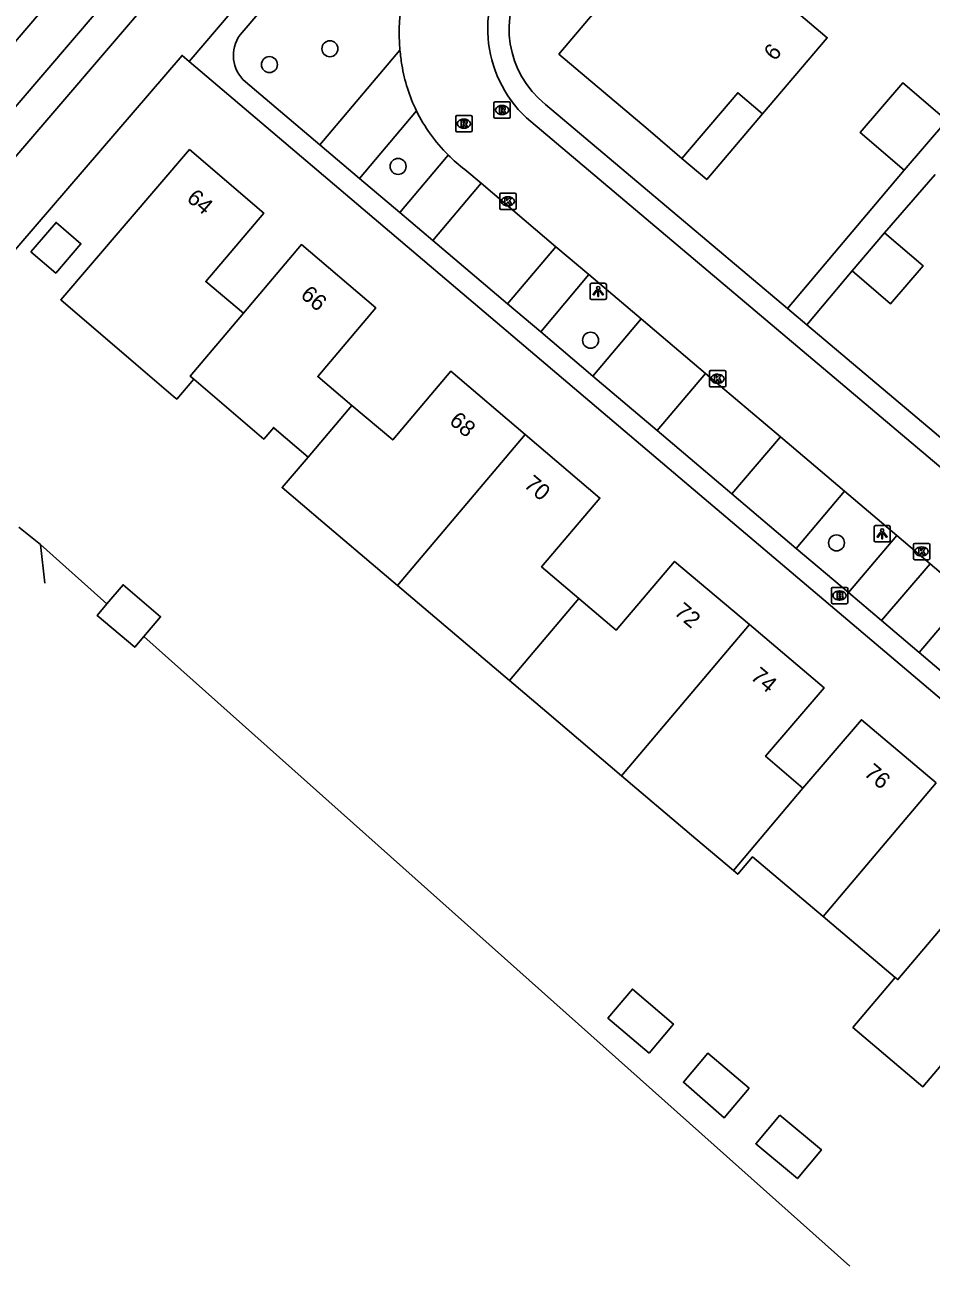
# Model space of a CAD drawing. Extents: x 156414 to 157775, y 382335 to 383765.
# Drawn here: x 156781.6 to 156837.1, y 382383.6 to 382459.6 of the extents above; entities that cross this region are included whole.
import ezdxf

# ---------------------------------------------------------------- set-up
doc = ezdxf.new("R2010")
doc.units = 0
for name, color, linetype in [('IMGEO_Boom', 7, 'Continuous'), ('IMGEO_Brandkraan', 7, 'Continuous'), ('IMGEO_Grasland_overig', 7, 'Continuous'), ('IMGEO_Groenvoorziening', 7, 'Continuous'), ('IMGEO_Kolk', 7, 'Continuous'), ('IMGEO_Lichtpunt', 7, 'Continuous'), ('IMGEO_Pand', 7, 'Continuous'), ('IMGEO_Pand_nummerreeks', 7, 'Continuous'), ('IMGEO_Pand_overbouw', 7, 'Continuous'), ('IMGEO_Parkeervlak_open', 7, 'Continuous'), ('IMGEO_Rijbaan_lokaal_open', 7, 'Continuous'), ('IMGEO_Rioolput', 7, 'Continuous'), ('IMGEO_Sloot', 7, 'Continuous'), ('IMGEO_Voetpad_open', 7, 'Continuous'), ('IMGEO_Waterloop', 7, 'Continuous')]:
    doc.layers.add(name, color=color, linetype=linetype)

msp = doc.modelspace()

# ---------------------------------------------------------------- linework, layer by layer
at = {"layer": 'IMGEO_Boom'}
for centre in [(156800.293, 382458.143), (156796.587, 382457.167), (156804.472, 382450.932), (156816.266, 382440.281), (156831.333, 382427.869)]:
    msp.add_circle(centre, 0.489, dxfattribs=at)
at = {"layer": 'IMGEO_Brandkraan'}
for p, q in [((156831.018, 382424.22), (156831.018, 382425.072)), ((156831.093, 382425.146), (156831.945, 382425.146)), ((156831.506, 382424.926), (156831.531, 382424.926)), ((156832.019, 382425.072), (156832.019, 382424.22)), ((156831.945, 382424.146), (156831.093, 382424.146)), ((156831.529, 382424.366), (156831.504, 382424.366))]:
    msp.add_line(p, q, dxfattribs=at)
for points in [[(156831.018, 382424.22), (156831.018, 382425.072)], [(156831.093, 382425.146), (156831.945, 382425.146)], [(156831.366, 382424.846), (156831.366, 382424.446), (156831.579, 382424.446)], [(156831.597, 382424.846), (156831.366, 382424.846)], [(156831.545, 382424.765), (156831.491, 382424.765), (156831.491, 382424.689)], [(156831.491, 382424.689), (156831.544, 382424.689)], [(156831.553, 382424.613), (156831.491, 382424.613), (156831.491, 382424.532)], [(156832.019, 382425.072), (156832.019, 382424.22)], [(156831.945, 382424.146), (156831.093, 382424.146)], [(156831.491, 382424.532), (156831.553, 382424.532)]]:
    msp.add_lwpolyline(points, dxfattribs=at)
for centre, radius, start, end in [((156831.095, 382425.07), 0.0765, 91.55205, 178.44795), ((156831.095, 382425.07), 0.0765, 91.55205, 178.44795), ((156831.546, 382424.727), 0.0379, 267.82845, 90.93552), ((156831.554, 382424.572), 0.0404, 269.87594, 90.50774), ((156831.601, 382424.701), 0.145, 59.4692, 91.53667), ((156831.626, 382424.748), 0.0922, 285.51372, 58.15012), ((156831.631, 382424.556), 0.105, 301.31148, 78.98903), ((156831.943, 382425.07), 0.0765, 1.55205, 88.44795), ((156831.943, 382425.07), 0.0765, 1.55205, 88.44795), ((156831.095, 382424.222), 0.0765, 181.55205, 268.44795), ((156831.095, 382424.222), 0.0765, 181.55205, 268.44795), ((156831.585, 382424.697), 0.251, 268.66757, 293.53466), ((156831.943, 382424.222), 0.0765, 271.55205, 358.44795), ((156831.943, 382424.222), 0.0765, 271.55205, 358.44795)]:
    msp.add_arc(centre, radius, start, end, dxfattribs=at)
for centre, major_axis, ratio, start_param, end_param in [((156831.505, 382424.646), (-0.387, 0.002), 0.722429, 4.712389, 7.853982), ((156831.53, 382424.646), (-0.39, 0.002), 0.717154, 1.570796, 4.712389)]:
    msp.add_ellipse(centre, major_axis=major_axis, ratio=ratio, start_param=start_param, end_param=end_param, dxfattribs=at)
at = {"layer": 'IMGEO_Grasland_overig'}
for points in [[(156786.631, 382424.138), (156782.557, 382427.77)], [(156832.144, 382383.561), (156788.885, 382422.128)]]:
    msp.add_lwpolyline(points, dxfattribs=at)
at = {"layer": 'IMGEO_Groenvoorziening'}
for points in [[(156820.95, 382498.966), (156818.053, 382495.021), (156800.704, 382474.383), (156791.599, 382463.885), (156773.907, 382443.229)], [(156772.208, 382435.618), (156791.237, 382457.729), (156791.675, 382457.364)]]:
    msp.add_lwpolyline(points, dxfattribs=at)
at = {"layer": 'IMGEO_Kolk'}
for p, q in [((156810.699, 382448.366), (156810.699, 382449.218)), ((156810.774, 382449.292), (156811.626, 382449.292)), ((156811.187, 382449.072), (156811.212, 382449.072)), ((156811.7, 382449.218), (156811.7, 382448.366)), ((156811.626, 382448.292), (156810.774, 382448.292)), ((156811.21, 382448.512), (156811.185, 382448.512)), ((156823.543, 382437.499), (156823.543, 382438.351)), ((156823.618, 382438.425), (156824.47, 382438.425)), ((156824.544, 382438.351), (156824.544, 382437.499)), ((156824.054, 382437.645), (156824.029, 382437.645)), ((156824.031, 382438.205), (156824.056, 382438.205)), ((156824.47, 382437.425), (156823.618, 382437.425)), ((156836.048, 382426.915), (156836.048, 382427.767)), ((156836.123, 382427.841), (156836.975, 382427.841)), ((156836.536, 382427.621), (156836.561, 382427.621)), ((156837.049, 382427.767), (156837.049, 382426.915)), ((156836.559, 382427.061), (156836.534, 382427.061)), ((156836.975, 382426.841), (156836.123, 382426.841))]:
    msp.add_line(p, q, dxfattribs=at)
for points in [[(156810.699, 382448.366), (156810.699, 382449.218)], [(156810.774, 382449.292), (156811.626, 382449.292)], [(156811.02, 382448.992), (156811.143, 382448.992), (156811.143, 382448.841), (156811.273, 382448.992), (156811.437, 382448.992), (156811.291, 382448.841), (156811.444, 382448.592), (156811.292, 382448.592), (156811.207, 382448.756), (156811.143, 382448.689), (156811.143, 382448.592), (156811.02, 382448.592), (156811.02, 382448.992)], [(156811.7, 382449.218), (156811.7, 382448.366)], [(156811.626, 382448.292), (156810.774, 382448.292)], [(156823.543, 382437.499), (156823.543, 382438.351)], [(156823.618, 382438.425), (156824.47, 382438.425)], [(156824.544, 382438.351), (156824.544, 382437.499)], [(156823.864, 382438.125), (156823.987, 382438.125), (156823.987, 382437.974), (156824.117, 382438.125), (156824.281, 382438.125), (156824.135, 382437.974), (156824.288, 382437.725), (156824.136, 382437.725), (156824.051, 382437.889), (156823.987, 382437.822), (156823.987, 382437.725), (156823.864, 382437.725), (156823.864, 382438.125)], [(156824.47, 382437.425), (156823.618, 382437.425)], [(156836.048, 382426.915), (156836.048, 382427.767)], [(156836.123, 382427.841), (156836.975, 382427.841)], [(156837.049, 382427.767), (156837.049, 382426.915)], [(156836.369, 382427.541), (156836.492, 382427.541), (156836.492, 382427.39), (156836.622, 382427.541), (156836.786, 382427.541), (156836.64, 382427.39), (156836.793, 382427.141), (156836.641, 382427.141), (156836.556, 382427.305), (156836.492, 382427.238), (156836.492, 382427.141), (156836.369, 382427.141), (156836.369, 382427.541)], [(156836.975, 382426.841), (156836.123, 382426.841)]]:
    msp.add_lwpolyline(points, dxfattribs=at)
for centre, start, end in [((156810.776, 382449.216), 91.55205, 178.44795), ((156810.776, 382449.216), 91.55205, 178.44795), ((156811.624, 382449.216), 1.55205, 88.44795), ((156811.624, 382449.216), 1.55205, 88.44795), ((156810.776, 382448.368), 181.55205, 268.44795), ((156810.776, 382448.368), 181.55205, 268.44795), ((156811.624, 382448.368), 271.55205, 358.44795), ((156811.624, 382448.368), 271.55205, 358.44795), ((156823.62, 382438.349), 91.55205, 178.44795), ((156823.62, 382438.349), 91.55205, 178.44795), ((156824.468, 382438.349), 1.55205, 88.44795), ((156824.468, 382438.349), 1.55205, 88.44795), ((156823.62, 382437.501), 181.55205, 268.44795), ((156823.62, 382437.501), 181.55205, 268.44795), ((156824.468, 382437.501), 271.55205, 358.44795), ((156824.468, 382437.501), 271.55205, 358.44795), ((156836.125, 382427.765), 91.55205, 178.44795), ((156836.125, 382427.765), 91.55205, 178.44795), ((156836.973, 382427.765), 1.55205, 88.44795), ((156836.973, 382427.765), 1.55205, 88.44795), ((156836.125, 382426.917), 181.55205, 268.44795), ((156836.125, 382426.917), 181.55205, 268.44795), ((156836.973, 382426.917), 271.55205, 358.44795), ((156836.973, 382426.917), 271.55205, 358.44795)]:
    msp.add_arc(centre, 0.0765, start, end, dxfattribs=at)
for centre, major_axis, ratio, start_param, end_param in [((156811.186, 382448.792), (-0.387, 0.002), 0.722429, 4.712389, 7.853982), ((156811.211, 382448.792), (-0.39, 0.002), 0.717154, 1.570796, 4.712389), ((156824.03, 382437.925), (-0.387, 0.002), 0.722429, 4.712389, 7.853982), ((156824.055, 382437.925), (-0.39, 0.002), 0.717154, 1.570796, 4.712389), ((156836.535, 382427.341), (-0.387, 0.002), 0.722429, 4.712389, 7.853982), ((156836.56, 382427.341), (-0.39, 0.002), 0.717154, 1.570796, 4.712389)]:
    msp.add_ellipse(centre, major_axis=major_axis, ratio=ratio, start_param=start_param, end_param=end_param, dxfattribs=at)
at = {"layer": 'IMGEO_Lichtpunt'}
for p, q in [((156816.236, 382443.677), (156816.236, 382442.87)), ((156816.236, 382443.677), (156816.236, 382442.87)), ((156817.138, 382443.772), (156816.33, 382443.772)), ((156817.138, 382443.772), (156816.33, 382443.772)), ((156817.232, 382442.87), (156817.232, 382443.677)), ((156817.232, 382442.87), (156817.232, 382443.677)), ((156816.33, 382442.776), (156817.138, 382442.776)), ((156816.33, 382442.776), (156817.138, 382442.776)), ((156833.632, 382428.832), (156833.632, 382428.025)), ((156833.632, 382428.832), (156833.632, 382428.025)), ((156834.534, 382428.927), (156833.726, 382428.927)), ((156834.534, 382428.927), (156833.726, 382428.927)), ((156834.628, 382428.025), (156834.628, 382428.832)), ((156834.628, 382428.025), (156834.628, 382428.832)), ((156833.726, 382427.931), (156834.534, 382427.931)), ((156833.726, 382427.931), (156834.534, 382427.931))]:
    msp.add_line(p, q, dxfattribs=at)
for points in [[(156816.61, 382443.341), (156816.649, 382443.313), (156816.461, 382443.051), (156816.423, 382443.078), (156816.61, 382443.341)], [(156816.712, 382443.293), (156816.759, 382443.293), (156816.759, 382442.971), (156816.712, 382442.971), (156816.712, 382443.293)], [(156816.822, 382443.313), (156816.86, 382443.34), (156817.047, 382443.078), (156817.008, 382443.05), (156816.822, 382443.313)], [(156834.006, 382428.496), (156834.045, 382428.468), (156833.857, 382428.206), (156833.819, 382428.233), (156834.006, 382428.496)], [(156834.108, 382428.448), (156834.155, 382428.448), (156834.155, 382428.126), (156834.108, 382428.126), (156834.108, 382428.448)], [(156834.218, 382428.468), (156834.256, 382428.495), (156834.443, 382428.233), (156834.404, 382428.205), (156834.218, 382428.468)]]:
    msp.add_lwpolyline(points, dxfattribs=at)
for centre in [(156816.735, 382443.475), (156834.131, 382428.63)]:
    msp.add_circle(centre, 0.0994, dxfattribs=at)
for centre, start, end in [((156816.33, 382443.677), 90, 180), ((156816.33, 382443.677), 90, 180), ((156817.138, 382443.677), 0, 90), ((156817.138, 382443.677), 0, 90), ((156816.33, 382442.87), 180, 270), ((156816.33, 382442.87), 180, 270), ((156817.138, 382442.87), 270, 0), ((156817.138, 382442.87), 270, 360), ((156833.726, 382428.832), 90, 180), ((156833.726, 382428.832), 90, 180), ((156834.534, 382428.832), 0, 90), ((156834.534, 382428.832), 0, 90), ((156833.726, 382428.025), 180, 270), ((156833.726, 382428.025), 180, 270), ((156834.534, 382428.025), 270, 0), ((156834.534, 382428.025), 270, 360)]:
    msp.add_arc(centre, 0.0946, start, end, dxfattribs=at)
at = {"layer": 'IMGEO_Pand'}
for points in [[(156823.603, 382464.901), (156821.52, 382462.535), (156819.671, 382464.14), (156814.326, 382457.818), (156819.783, 382453.194), (156821.862, 382451.425), (156825.278, 382455.442), (156826.802, 382454.147), (156830.766, 382458.81), (156823.603, 382464.901)], [(156838.087, 382453.751), (156835.405, 382456.06), (156832.784, 382453.003), (156835.48, 382450.702)], [(156838.087, 382453.751), (156835.48, 382450.702)], [(156791.957, 382437.897), (156790.909, 382436.674), (156790.691, 382436.861), (156788.408, 382438.819), (156783.803, 382442.767), (156791.692, 382451.968), (156796.235, 382448.073), (156792.687, 382443.876), (156794.997, 382441.95)], [(156781.972, 382445.705), (156783.516, 382447.506), (156785.042, 382446.198), (156783.497, 382444.397), (156781.972, 382445.705)], [(156834.276, 382446.87), (156832.298, 382444.54)], [(156832.298, 382444.54), (156834.638, 382442.513), (156836.632, 382444.85), (156834.276, 382446.87)], [(156794.997, 382441.95), (156798.545, 382446.146), (156803.106, 382442.264), (156799.551, 382438.056), (156801.645, 382436.286)], [(156794.997, 382441.95), (156791.731, 382438.091), (156791.957, 382437.897)], [(156801.645, 382436.286), (156804.14, 382434.178), (156807.696, 382438.387), (156812.265, 382434.503)], [(156798.968, 382433.123), (156796.887, 382434.907), (156796.85, 382434.939), (156796.239, 382434.225), (156791.957, 382437.897)], [(156798.968, 382433.123), (156801.645, 382436.286)], [(156812.265, 382434.503), (156804.439, 382425.255)], [(156812.265, 382434.503), (156816.834, 382430.618), (156813.267, 382426.411), (156815.548, 382424.466)], [(156804.439, 382425.255), (156799.87, 382429.132), (156797.367, 382431.255), (156798.968, 382433.123)], [(156815.548, 382424.466), (156817.829, 382422.522), (156821.414, 382426.737), (156825.995, 382422.864)], [(156786.631, 382424.138), (156787.618, 382425.302), (156789.921, 382423.349), (156788.885, 382422.128)], [(156811.294, 382419.439), (156809.01, 382421.376), (156804.439, 382425.255)], [(156788.885, 382422.128), (156788.332, 382421.476), (156786.03, 382423.429), (156786.631, 382424.138)], [(156815.548, 382424.466), (156811.294, 382419.439)], [(156825.995, 382422.864), (156818.164, 382413.609)], [(156825.995, 382422.864), (156830.576, 382418.991), (156826.992, 382414.794), (156829.278, 382412.835)], [(156818.164, 382413.609), (156813.581, 382417.498), (156811.294, 382419.439)], [(156829.278, 382412.835), (156832.862, 382417.032), (156837.437, 382413.161)], [(156825.016, 382407.795), (156822.721, 382409.742), (156818.164, 382413.609)], [(156825.016, 382407.795), (156829.278, 382412.835)], [(156830.519, 382404.985), (156837.437, 382413.161)], [(156830.519, 382404.985), (156826.195, 382408.644), (156825.284, 382407.567), (156825.016, 382407.795)], [(156842.012, 382409.29), (156835.093, 382401.114), (156834.934, 382401.249)], [(156834.934, 382401.249), (156830.519, 382404.985)], [(156839.668, 382397.243), (156839.223, 382397.62), (156836.63, 382394.555), (156832.341, 382398.184), (156834.934, 382401.249)], [(156819.849, 382396.616), (156817.331, 382398.761), (156818.83, 382400.533), (156821.339, 382398.389), (156819.849, 382396.616)], [(156825.976, 382394.472), (156824.452, 382392.657), (156821.95, 382394.826), (156823.457, 382396.614), (156825.976, 382394.472)], [(156827.866, 382392.822), (156830.411, 382390.691), (156828.934, 382388.931), (156826.381, 382391.059), (156827.866, 382392.822)]]:
    msp.add_lwpolyline(points, dxfattribs=at)
at = {"layer": 'IMGEO_Pand_overbouw'}
msp.add_lwpolyline([(156821.862, 382451.425), (156823.386, 382450.129), (156826.802, 382454.147), (156825.278, 382455.442)], close=True, dxfattribs=at)
at = {"layer": 'IMGEO_Parkeervlak_open'}
for points in [[(156799.666, 382452.263), (156804.586, 382458.056)], [(156805.592, 382454.345), (156802.099, 382450.202)], [(156807.536, 382451.631), (156804.578, 382448.103)], [(156816.15, 382444.311), (156813.213, 382440.791)], [(156816.404, 382438.089), (156819.362, 382441.59)], [(156831.828, 382431.028), (156828.869, 382427.532)], [(156832.065, 382424.824), (156835.024, 382428.321)]]:
    msp.add_lwpolyline(points, dxfattribs=at)
at = {"layer": 'IMGEO_Rijbaan_lokaal_open'}
for points in [[(156848.473, 382423.417), (156812.607, 382453.674)], [(156808.554, 382450.748), (156809.556, 382449.899)], [(156809.556, 382449.899), (156806.596, 382446.395)], [(156814.14, 382446.014), (156809.556, 382449.899)], [(156806.596, 382446.395), (156811.181, 382442.512)], [(156811.181, 382442.512), (156814.14, 382446.014)], [(156814.14, 382446.014), (156816.15, 382444.311)], [(156816.15, 382444.311), (156819.362, 382441.59)], [(156819.362, 382441.59), (156823.304, 382438.249)], [(156823.304, 382438.249), (156820.341, 382434.755)], [(156827.897, 382434.359), (156823.304, 382438.249)], [(156820.341, 382434.755), (156822.632, 382432.815), (156824.929, 382430.869)], [(156824.929, 382430.869), (156827.897, 382434.359)], [(156827.897, 382434.359), (156831.828, 382431.028)], [(156831.828, 382431.028), (156835.024, 382428.321)], [(156835.024, 382428.321), (156837.066, 382426.591)], [(156837.066, 382426.591), (156834.091, 382423.107)], [(156839.363, 382424.645), (156837.066, 382426.591)], [(156836.388, 382421.161), (156839.363, 382424.645)], [(156834.091, 382423.107), (156836.388, 382421.161)]]:
    msp.add_lwpolyline(points, dxfattribs=at)
for centre, radius, start, end in [((156816.088, 382459.104), 11.549, 150.47664, 185.20497), ((156817.438, 382459.378), 7.475, 144.45351, 229.73758), ((156816.681, 382459.188), 12.148, 185.34836, 189.64991), ((156814.618, 382458.741), 10.04, 189.10591, 205.96671), ((156814.578, 382458.729), 9.998, 206.0032, 225.22378), ((156814.491, 382458.621), 9.86, 225.14377, 232.98034)]:
    msp.add_arc(centre, radius, start, end, dxfattribs=at)
at = {"layer": 'IMGEO_Rioolput'}
for p, q in [((156810.34, 382453.962), (156810.34, 382454.814)), ((156810.415, 382454.888), (156811.267, 382454.888)), ((156810.828, 382454.668), (156810.853, 382454.668)), ((156811.341, 382454.814), (156811.341, 382453.962)), ((156808.003, 382453.126), (156808.003, 382453.978)), ((156808.078, 382454.052), (156808.93, 382454.052)), ((156808.491, 382453.832), (156808.516, 382453.832)), ((156809.004, 382453.978), (156809.004, 382453.126)), ((156811.267, 382453.888), (156810.415, 382453.888)), ((156810.851, 382454.108), (156810.826, 382454.108)), ((156808.93, 382453.052), (156808.078, 382453.052)), ((156808.514, 382453.272), (156808.489, 382453.272))]:
    msp.add_line(p, q, dxfattribs=at)
for points in [[(156810.34, 382453.962), (156810.34, 382454.814)], [(156810.415, 382454.888), (156811.267, 382454.888)], [(156810.929, 382454.586), (156810.677, 382454.588), (156810.677, 382454.188)], [(156810.677, 382454.188), (156810.801, 382454.188), (156810.801, 382454.35), (156810.812, 382454.35)], [(156810.855, 382454.507), (156810.801, 382454.507), (156810.801, 382454.426)], [(156810.801, 382454.426), (156810.853, 382454.426)], [(156810.859, 382454.321), (156810.93, 382454.188), (156811.07, 382454.188), (156811.005, 382454.314)], [(156811.341, 382454.814), (156811.341, 382453.962)], [(156808.003, 382453.126), (156808.003, 382453.978)], [(156808.078, 382454.052), (156808.93, 382454.052)], [(156808.592, 382453.75), (156808.34, 382453.752), (156808.34, 382453.352)], [(156808.34, 382453.352), (156808.464, 382453.352), (156808.464, 382453.514), (156808.475, 382453.514)], [(156808.518, 382453.671), (156808.464, 382453.671), (156808.464, 382453.59)], [(156808.464, 382453.59), (156808.516, 382453.59)], [(156808.522, 382453.485), (156808.593, 382453.352), (156808.733, 382453.352), (156808.668, 382453.478)], [(156809.004, 382453.978), (156809.004, 382453.126)], [(156811.267, 382453.888), (156810.415, 382453.888)], [(156808.93, 382453.052), (156808.078, 382453.052)]]:
    msp.add_lwpolyline(points, dxfattribs=at)
for centre, radius, start, end in [((156810.417, 382454.812), 0.0765, 91.55205, 178.44795), ((156810.417, 382454.812), 0.0765, 91.55205, 178.44795), ((156810.811, 382454.297), 0.0533, 26.02933, 88.69889), ((156810.837, 382454.615), 0.19, 274.7715, 282.96867), ((156810.861, 382454.411), 0.0964, 77.00612, 93.18647), ((156810.875, 382454.468), 0.0378, 276.66336, 79.67722), ((156810.928, 382454.476), 0.109, 350.36119, 89.41601), ((156810.926, 382454.476), 0.112, 277.58423, 350.98172), ((156810.91, 382454.261), 0.108, 29.51342, 73.79051), ((156811.265, 382454.812), 0.0765, 1.55205, 88.44795), ((156811.265, 382454.812), 0.0765, 1.55205, 88.44795), ((156808.08, 382453.976), 0.0765, 91.55205, 178.44795), ((156808.08, 382453.976), 0.0765, 91.55205, 178.44795), ((156808.474, 382453.461), 0.0533, 26.02933, 88.69889), ((156808.5, 382453.779), 0.19, 274.7715, 282.96867), ((156808.524, 382453.575), 0.0964, 77.00612, 93.18647), ((156808.538, 382453.632), 0.0378, 276.66336, 79.67722), ((156808.591, 382453.64), 0.109, 350.36119, 89.41601), ((156808.589, 382453.64), 0.112, 277.58423, 350.98172), ((156808.573, 382453.425), 0.108, 29.51342, 73.79051), ((156808.928, 382453.976), 0.0765, 1.55205, 88.44795), ((156808.928, 382453.976), 0.0765, 1.55205, 88.44795), ((156810.417, 382453.964), 0.0765, 181.55205, 268.44795), ((156810.417, 382453.964), 0.0765, 181.55205, 268.44795), ((156811.265, 382453.964), 0.0765, 271.55205, 358.44795), ((156811.265, 382453.964), 0.0765, 271.55205, 358.44795), ((156808.08, 382453.128), 0.0765, 181.55205, 268.44795), ((156808.08, 382453.128), 0.0765, 181.55205, 268.44795), ((156808.928, 382453.128), 0.0765, 271.55205, 358.44795), ((156808.928, 382453.128), 0.0765, 271.55205, 358.44795)]:
    msp.add_arc(centre, radius, start, end, dxfattribs=at)
for centre, major_axis, ratio, start_param, end_param in [((156810.827, 382454.388), (-0.387, 0.002), 0.722429, 4.712389, 7.853982), ((156810.852, 382454.388), (-0.39, 0.002), 0.717154, 1.570796, 4.712389), ((156808.49, 382453.552), (-0.387, 0.002), 0.722429, 4.712389, 7.853982), ((156808.515, 382453.552), (-0.39, 0.002), 0.717154, 1.570796, 4.712389)]:
    msp.add_ellipse(centre, major_axis=major_axis, ratio=ratio, start_param=start_param, end_param=end_param, dxfattribs=at)
at = {"layer": 'IMGEO_Sloot'}
for points in [[(156782.557, 382427.77), (156781.23, 382428.836)], [(156782.828, 382425.407), (156782.557, 382427.77)]]:
    msp.add_lwpolyline(points, dxfattribs=at)
at = {"layer": 'IMGEO_Voetpad_open'}
for points in [[(156791.675, 382457.364), (156810.572, 382479.519), (156831.533, 382504.167)], [(156794.793, 382458.992), (156802.386, 382467.905)], [(156876.247, 382385.72), (156849.783, 382408.111), (156821.763, 382431.828), (156791.675, 382457.364)], [(156799.666, 382452.263), (156795.115, 382456.117)], [(156828.335, 382442.229), (156813.512, 382454.727)], [(156802.099, 382450.202), (156799.666, 382452.263)], [(156835.48, 382450.702), (156828.335, 382442.229)], [(156834.276, 382446.87), (156837.386, 382450.444)], [(156804.578, 382448.103), (156802.099, 382450.202)], [(156806.596, 382446.395), (156804.578, 382448.103)], [(156829.512, 382441.236), (156832.298, 382444.54)], [(156813.213, 382440.791), (156811.181, 382442.512)], [(156829.512, 382441.236), (156828.335, 382442.229)], [(156816.404, 382438.089), (156813.213, 382440.791)], [(156849.402, 382424.466), (156829.512, 382441.236)], [(156820.341, 382434.755), (156816.404, 382438.089)], [(156828.869, 382427.532), (156824.929, 382430.869)], [(156832.065, 382424.824), (156828.869, 382427.532)], [(156834.091, 382423.107), (156832.065, 382424.824)], [(156840.297, 382417.85), (156836.388, 382421.161)]]:
    msp.add_lwpolyline(points, dxfattribs=at)
for centre, radius, start, end in [((156817.203, 382459.372), 5.933, 146.44628, 231.52496), ((156796.52, 382457.73), 2.139, 143.84249, 228.9385)]:
    msp.add_arc(centre, radius, start, end, dxfattribs=at)
at = {"layer": 'IMGEO_Waterloop'}
msp.add_lwpolyline([(156769.56, 382445.166), (156771.428, 382443.383), (156818.52, 382498.415), (156816.396, 382500.028), (156769.56, 382445.166)], dxfattribs=at)

# ---------------------------------------------------------------- texts
at = {"layer": 'IMGEO_Pand_nummerreeks'}
for s, rotation, p in [('6', 49.4348, (156827.548, 382457.343)), ('64', 319.38875, (156791.456, 382448.878)), ('66', 319.60075, (156798.429, 382442.961)), ('68', 319.63512, (156807.543, 382435.235)), ('70', 319.63512, (156812.117, 382431.347)), ('72', 319.78409, (156821.321, 382423.542)), ('74', 319.78409, (156826.006, 382419.581)), ('76', 319.76272, (156832.956, 382413.678))]:
    msp.add_text(s, height=1, rotation=rotation, dxfattribs=at).set_placement(p)

doc.saveas('drawing.dxf')
